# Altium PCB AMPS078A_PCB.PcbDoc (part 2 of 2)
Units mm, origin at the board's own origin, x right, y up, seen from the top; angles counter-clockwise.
Board outline 85 x 120 mm, 4 copper layers (Top Layer, Signal Layer 1, Signal Layer 2, Bottom Layer), stack 1.567 mm thick; 105 components, 52 nets, 354 pads, 440 vias.
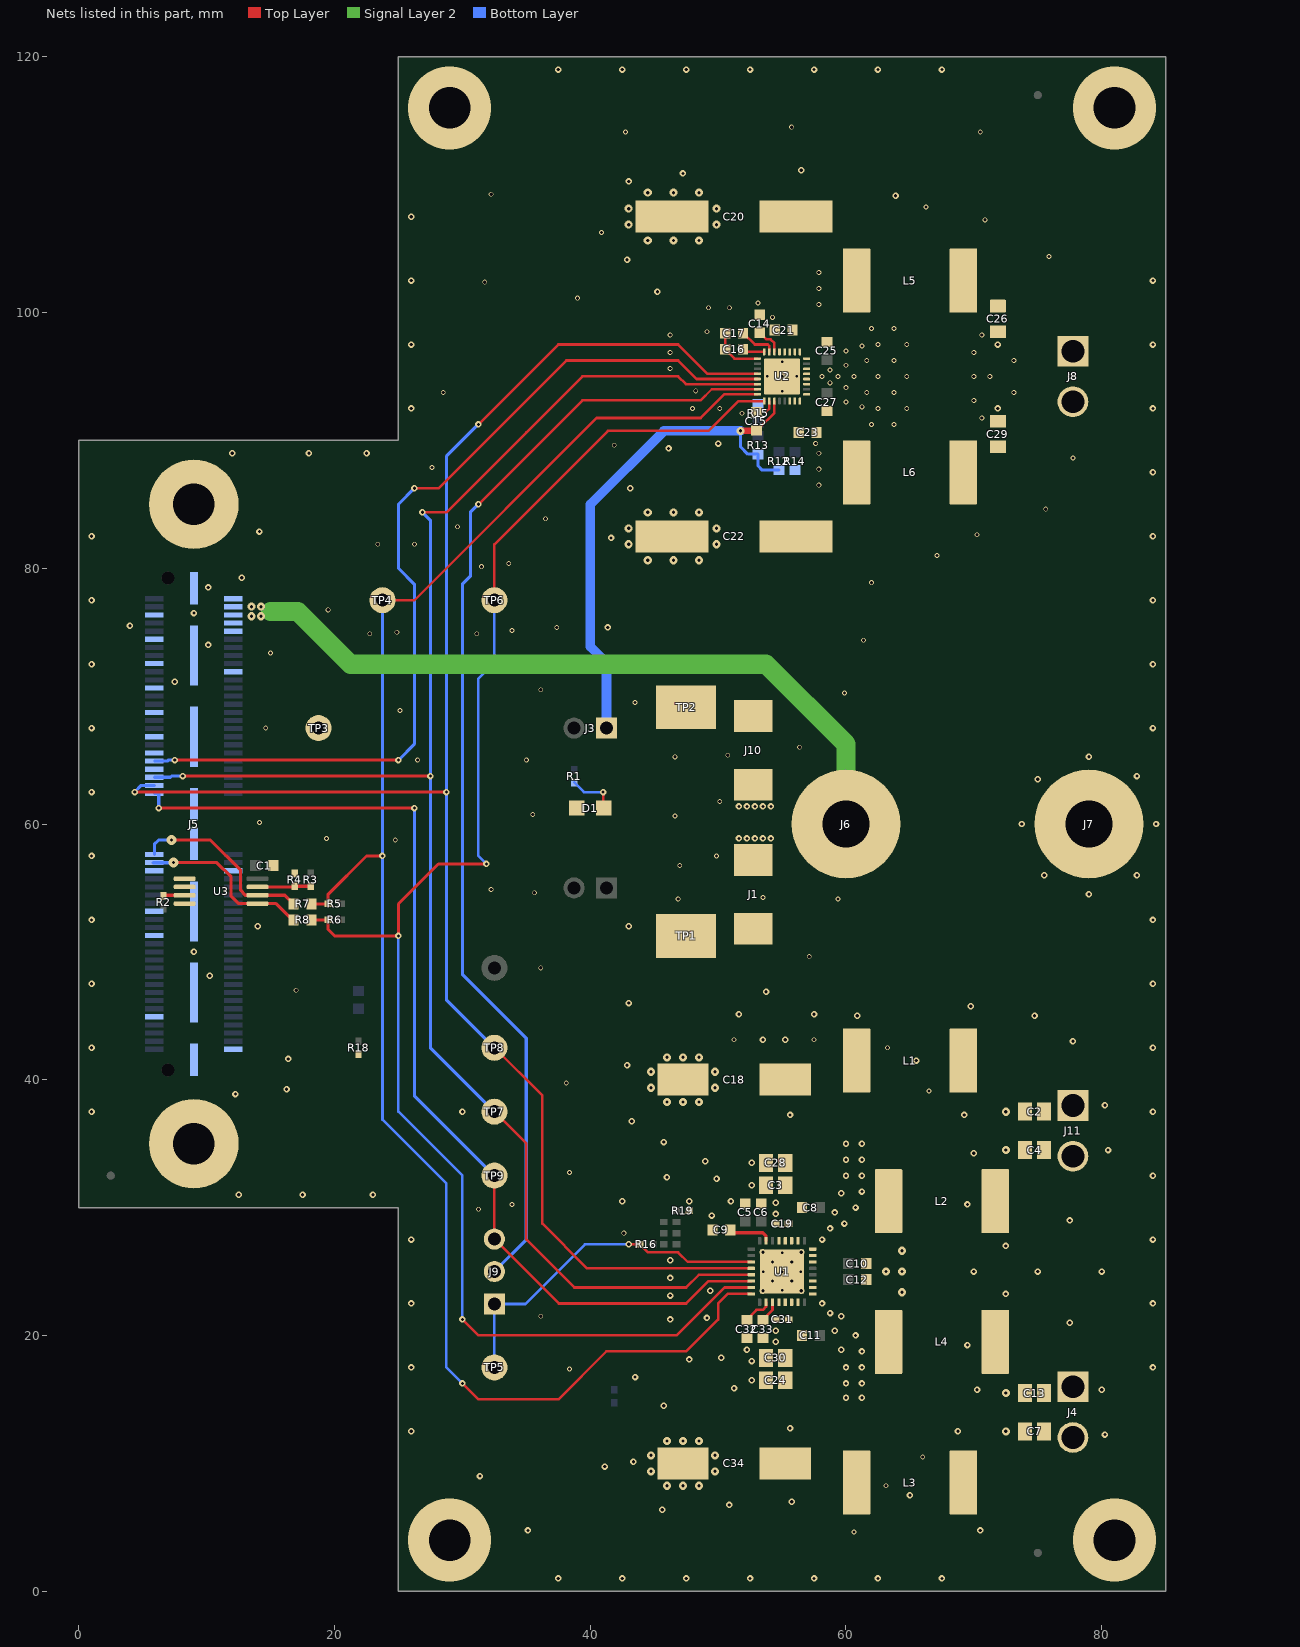
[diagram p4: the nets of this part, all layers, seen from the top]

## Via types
v1: diameter 0.508, hole 0.254, Top Layer to Bottom Layer, tented both sides, 228 vias
v2: diameter 0.381, hole 0.254, Top Layer to Bottom Layer, tented both sides, 125 vias
v3: diameter 0.635, hole 0.254, Top Layer to Bottom Layer, tented both sides, 61 vias
v4: diameter 0.5, hole 0.2, Top Layer to Bottom Layer, 10 vias
v5: diameter 0.508, hole 0.254, Top Layer to Bottom Layer, 8 vias
v6: diameter 6.5, hole 3.25, Top Layer to Bottom Layer, tented both sides, 4 vias
v7: diameter 0.762, hole 0.254, Top Layer to Bottom Layer, tented both sides, 4 vias

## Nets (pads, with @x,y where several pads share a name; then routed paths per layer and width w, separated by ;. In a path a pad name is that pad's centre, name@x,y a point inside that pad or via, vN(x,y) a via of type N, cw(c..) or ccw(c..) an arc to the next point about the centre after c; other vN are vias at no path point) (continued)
DVDD2: C15.1 J3.1 R12.2 R13.2 U2.11 | length 41.9
  Top Layer w0.2: C15.1@53,90.8 53.2,91 53.25,91 54.4,92.15 U2.11@54.4,93.075
  Top Layer w0.25: C15.1@52.95,90.75 C15.1@53,90.8
  Top Layer w0.5: v3(51.75,90.75) C15.1@52.95,90.75
  Bottom Layer w0.25: v3(51.75,90.75) 51.75,89.5 52.325,88.925 R13.2@53.125,88.925 53.125,88 53.45,87.675 R12.2@54.75,87.675
  Bottom Layer w0.75: J3.1@41.27,67.5 41.27,72.605 40,73.875 40,85 45.75,90.75 v3(51.75,90.75)
GND: C1.2 C2.2 C3.1 C4.2 C5.1 C6.2 C7.2 C9.2 C13.2 C14.2 C15.2 C18.2 C19.2 C20.2 C21.2 C22.2 C23.2 C24.1 C26.2 C28.1 C29.2 C30.1 C31.2 C32.2 C33.2 C34.2 D1.2 J5.5 J5.10 J5.11 J5.17 J5.20 J5.23 J5.29 J5.35 J5.39 J5.43 J5.55 J5.56 J5.65 J5.71 J5.91 J5.100 J5.101 J5.102 J5.103 J5.104 J5.105 J5.106 J5.107 J5.108 J7.1 pad.0 R4.1 R14.1 R15.1 R18.1 R19.2 TP3.1 U1.5 U1.20 U1.25 U1.26 U1.31 U1.32 U1.33 U2.10 U2.19 U2.20 U2.21 U2.22 U2.29 U2.33@55,95 U3.1 U3.2 U3.4 | length 0.9
  Top Layer w0.2: 53.75,92.25 54,92.5 U2.10@54,93.075
  other v1: 37.5,1 42.5,1 47.5,1 52.5,1 57.5,1 62.5,1 67.5,1 35.125,4.75 70.5,4.75 45.625,6.375 50.875,6.75 55.75,7 65,7.5 31.375,9 41.125,9.75 43.375,10.125 80.25,12.25 26,12.5 68.75,12.5 55.625,12.75 45.75,14.5 60,15.125 61.25,15.125 70.25,15.75 80,15.75 51.25,15.875 60,16.25 61.25,16.25 52.625,16.5 43.5,16.75 26,17.5 60,17.5 61.25,17.5 84,17.5 52.625,18 47.75,18.125 50.25,18.25 61.25,18.75 52.25,18.875 59.625,18.875 69.5,19.25 54.5,19.5 60.75,20 54.5,20.375 59.125,20.375 77.5,21 46.25,21.25 49.125,21.375 59.625,21.5 58.75,21.75 26,22.5 58.125,22.5 84,22.5 46.25,23.125 72.5,23.25 49.375,23.5 46.25,24.5 70,25 75,25 80,25 46.25,25.875 72.5,27 26,27.5 58.125,27.5 84,27.5 58.75,28.375 59.875,28.75 77.5,29 49.5,29.375 54.5,29.5 59.125,29.625 60.75,30 69.5,30.25 54.5,30.375 42.5,30.5 47.75,30.5 51,30.5 12.5,31 17.5,31 23,31 59.625,31.125 61.25,31.25 52.625,31.75 49.875,32.25 46,32.375 60,32.5 61.25,32.5 84,32.5 52.625,33.5 49,33.625 60,33.75 61.25,33.75 70,34.25 80.5,34.5 60,35 61.25,35 45.75,35.125 43.25,36.75 55.625,37.25 69.25,37.25 1,37.5 30,37.5 84,37.5 80.25,38 12.25,38.875 16.25,39.25 42.875,41.125 65.5,41.5 16.375,41.625 1,42.5 84,42.5 77.75,43 53.5,43.125 55.25,43.125 60.875,45 74.75,45 51.625,45.125 57.5,45.125 69.75,45.75 43,46 53.75,46.875 1,47.5 84,47.5 10.25,48.125 9,50 14,52 43,52 1,52.5 84,52.5 79,54.5 75.5,56 82.75,56 1,57.5 73.75,60 84.25,60 1,62.5 75,63.5 82.75,63.75 79,65.25 1,67.5 84,67.5 7.5,71.125 1,72.5 84,72.5 10.125,74 41.375,75.375 4,75.5 9,76.5 1,77.5 84,77.5 10.125,78.5 12.75,79.25 41.625,82.375 1,82.5 84,82.5 14.125,82.875 43.125,86.25 84,87.5 12,89 18,89 22.5,89 46.125,89.375 50,89.75 26,92.5 71.875,92.5 84,92.5 26,97.5 71.875,97.5 84,97.5 45.25,101.625 26,102.5 84,102.5 42.875,104.125 26,107.5 63.875,109.125 43,110.25 47.25,110.875 56.5,111.125 37.5,119 42.5,119 47.5,119 52.5,119 57.5,119 62.5,119 67.5,119
  other v2: 60.625,4.625 63.125,8.25 66,10.5 38.375,17.375 36.125,21.5 42.625,28 31.25,29.875 33.875,30.25 38.375,32.75 66.5,39.125 38.125,39.75 63.25,42.5 51.25,43.125 57.5,43.125 17,47 36.125,48.75 57.125,49.625 46.875,54.125 59.375,54.125 53.5,54.25 35.625,54.625 32.25,54.875 47,56.75 49.875,57.5 24.75,58.75 19.375,58.875 14.125,60.125 46.625,60.625 35.5,60.75 50.125,61.75 26.5,65 35,65 46.625,65.25 50.75,65.375 56.375,66 14.625,67.5 25.125,68.875 43.5,69.5 59.875,70.25 36.125,70.5 15,73.375 61.375,74.375 22.75,74.875 31.125,74.875 24.875,75 33.875,75.125 37.375,75.375 19.5,76.75 62,78.875 31.5,80.125 33.625,80.375 67.125,81 23.375,81.875 26.25,81.875 70.25,82.625 29.625,83.25 36.5,83.875 75.625,84.625 57.875,86.5 57.875,87.75 27.625,87.875 77.75,88.625 57.875,89 41.875,89.625 57.625,89.75 62,91.25 63.75,91.25 70.625,91.75 51.875,92.125 48,92.5 50.125,92.5 62.5,92.5 64.75,92.5 61.25,92.625 60,93 70,93.125 28.5,93.75 61.625,93.75 63.75,93.75 73.125,93.75 48.25,93.875 60,94.125 58.75,94.5 58.125,95 59.375,95 60.625,95 62.5,95 64.75,95 70,95 71.25,95 77.5,95 58.75,95.5 46.25,95.625 60,95.875 61.625,96.25 63.75,96.25 73.125,96.25 46.25,96.875 70,96.875 60,97 61.25,97.375 62.5,97.5 64.75,97.5 46.25,98.25 70.625,98.25 49.125,98.5 62,98.75 63.75,98.75 54.25,99.625 49.25,100.375 50.875,100.375 57.875,100.625 53.125,100.75 39,101.125 57.875,101.875 31.75,102.375 57.875,103.125 75.875,104.375 40.875,106.25 70.875,107.25 66.25,108.25 32.25,109.25 42.75,114.125 70.5,114.125 55.75,114.5
  other v3: 72.5,12.5 72.5,15.5 64.375,23.375 63.125,25 64.375,25 64.375,26.625 72.5,34.5 72.5,37.5
  other v4: 55,23.525 53.525,25 55,25 56.475,25 55,26.475 55,93.85 53.85,95 55,95 56.15,95 55,96.15
  other v5: 53.5,23.5 56.5,23.5 54.25,24.25 55.75,24.25 54.25,25.75 55.75,25.75 53.5,26.5 56.5,26.5
  other v6: 29,4 81,4 29,116 81,116
Left+: C2.1 J11.1 L1.2
Left-: C4.1 J11.2 L2.2
LRCLK: J5.47 TP8.1 U1.12 U2.4 | length 135.9
  Top Layer w0.2: v1(31.25,91.25) 37.5,97.5 46.875,97.5 49.175,95.2 U2.4@53.075,95.2 ; TP8.1@32.5,42.5 36.25,38.75 36.25,28.75 39.75,25.25 U1.12@52.6,25.25
  Top Layer w0.25: v1(4.375,62.5) v1(28.75,62.5)
  Bottom Layer w0.25: v1(4.375,62.5) 4.891,63.016 J5.47@5.914,63.016 ; v1(31.25,91.25) 28.75,88.75 v1(28.75,62.5) 28.75,46.25 TP8.1@32.5,42.5
MCLK: J5.41 U2.5 | length 73.5
  Top Layer w0.2: v1(26.25,86.25) 28.125,86.25 38.125,96.25 46.875,96.25 48.325,94.8 U2.5@53.075,94.8
  Top Layer w0.25: v1(7.5,65) v1(25,65)
  Bottom Layer w0.25: J5.41@5.914,64.921 6.921,64.921 7,65 v1(7.5,65) ; v1(25,65) 26.25,66.25 26.25,78.75 25,80 25,85 v1(26.25,86.25)
NetC9_1: C9.1 U1.7 | length 3.4
  Top Layer w0.254: C9.1@50.95,28.25 51.173,28.027 53.481,28.027 53.75,27.758 U1.7@53.75,27.4
NetC14_1: C14.1 U2.30 | length 2.2
  Top Layer w0.2: C14.1@53.25,98.425 53.775,97.9 54.1,97.9 54.4,97.6 U2.30@54.4,96.925
NetC16_1: C16.1 C17.1 U2.1 | length 4.1
  Top Layer w0.2: C17.1@50.55,98.375 C16.1@50.55,97.125 51.275,96.4 U2.1@53.075,96.4
NetC16_2: C16.2 U2.32 | length 1.7
  Top Layer w0.2: C16.2@51.95,97.125 52.15,96.925 U2.32@53.6,96.925
NetC17_2: C17.2 U2.31 | length 2.9
  Top Layer w0.2: C17.2@51.95,98.375 52,98.375 52.875,97.5 53.875,97.5 54,97.375 U2.31@54,96.925
NetC32_1: C32.1 U1.18 | length 2.3
  Top Layer w0.2: C32.1@52.25,21.2 52.25,21.25 53,22 53.5,22 53.75,22.25 U1.18@53.75,22.6
NetC33_1: C33.1 U1.19 | length 1.7
  Top Layer w0.2: C33.1@53.5,21.2 53.5,21.25 54.25,22 U1.19@54.25,22.6
NetD1_1: D1.1 R1.1 | length 3.8
  Top Layer w0.2: v1(41,62.5) 41,61.3 D1.1@41.05,61.25
  Bottom Layer w0.2: R1.1@38.75,63.25 39.5,62.5 v1(41,62.5)
NetR2_1: R2.1 U3.3 | length 1.7
  Top Layer w0.25: R2.1@6.625,54.375 6.675,54.425 U3.3@8.275,54.425
NetR3_2: R3.2 R4.2 U3.7 | length 4.2
  Top Layer w0.254: U3.7@13.975,55.075 16.7,55.075 R4.2@16.875,55.25 ; R4.2@16.875,55.125 R3.2@18.125,55.125
OUT_A+: C8.2 L1.1 U1.2
OUT_A-: C10.2 L2.1 U1.30
OUT_B+: C11.2 L3.1 U1.23
OUT_B-: C12.2 L4.1 U1.27
OUT_N: C27.2 L6.1 U2.16 U2.17
OUT_P: C25.2 L5.1 U2.24 U2.25
PVDD: J1.1 J5.2 J5.4 J5.6 J5.8 J6.1 J10.1 | length 55.5
  Signal Layer 2 w1.5: 15,76.625 17.125,76.625 21.25,72.5 53.75,72.5 60,66.25 J6.1@60,60
  other v1: 51.625,58.875 52.25,58.875 52.875,58.875 53.5,58.875 54.125,58.875 51.625,61.375 52.25,61.375 52.875,61.375 53.5,61.375 54.125,61.375
  other v3: 13.5,76.25 14.25,76.25 13.5,77 14.25,77
PVDD1: C3.2 C18.1 C19.1 C24.2 C28.2 C30.2 C31.1 C34.1 J1.2 TP1.1 U1.3 U1.4 U1.21 U1.22
  other v3: 46,8.25 47.25,8.25 48.5,8.25 44.75,9.375 49.75,9.375 44.75,10.625 49.75,10.625 46,11.75 47.25,11.75 48.5,11.75 46,38.25 47.25,38.25 48.5,38.25 44.75,39.375 49.75,39.375 44.75,40.625 49.75,40.625 46,41.75 47.25,41.75 48.5,41.75
PVDD2: C20.1 C21.1 C22.1 C23.1 J10.2 TP2.1 U2.14 U2.15 U2.26 U2.27 U2.28
  other v3: 44.5,80.625 46.5,80.625 48.5,80.625 43,81.875 49.875,81.875 43,83.125 49.875,83.125 44.5,84.375 46.5,84.375 48.5,84.375 44.5,105.625 46.5,105.625 48.5,105.625 43,106.875 49.875,106.875 43,108.125 49.875,108.125 44.5,109.375 46.5,109.375 48.5,109.375
Right+: C7.1 J4.2 L3.2
Right-: C13.1 J4.1 L4.2
SCL: R5.1 R7.1 TP4.1 U1.16 U2.8 | length 134.6
  Top Layer w0.2: TP4.1@23.75,77.5 26.25,77.5 40.5,91.75 48.625,91.75 50.475,93.6 U2.8@53.075,93.6 ; v1(30,16.25) 31.25,15 37.5,15 41.25,18.75 47.5,18.75 50,21.25 50,22.5 50.75,23.25 U1.16@52.6,23.25
  Top Layer w0.25: R7.1@18.2,53.75 R5.1@19.5,53.75 19.5,54.5 22.5,57.5 v1(23.75,57.5)
  Bottom Layer w0.2: TP4.1@23.75,77.5 v1(23.75,57.5) 23.75,36.875 28.75,31.875 28.75,17.5 v1(30,16.25)
SCL-PPCMB_OUT: J5.51 R7.2 U3.6 | length 15.8
  Top Layer w0.25: v7(7.25,58.75) 10.279,58.75 12.649,56.38 12.649,54.805 ; 13.024,54.43 16.12,54.43 R7.2@16.8,53.75
  Top Layer w0.254: 12.649,54.805 13.024,54.43 13.029,54.425 U3.6@13.975,54.425
  Bottom Layer w0.254: J5.51@5.914,57.619 5.914,58.414 6.25,58.75 v7(7.25,58.75)
SCLK: J5.45 TP7.1 U1.13 U2.6 | length 132.3
  Top Layer w0.2: v1(26.875,84.375) 28.75,84.375 35,90.625 39.375,95 46.875,95 47.475,94.4 U2.6@53.075,94.4 ; TP7.1@32.5,37.5 35,35 35,27.5 38.75,23.75 47.5,23.75 48.5,24.75 U1.13@52.6,24.75
  Top Layer w0.25: v1(8.125,63.75) v1(27.5,63.75)
  Bottom Layer w0.25: J5.45@5.914,63.651 7.151,63.651 7.25,63.75 v1(8.125,63.75) ; v1(26.875,84.375) 27.5,83.75 v1(27.5,63.75) 27.5,42.5 TP7.1@32.5,37.5
SDA: R6.1 R8.1 TP6.1 U1.15 U2.9 | length 126.7
  Top Layer w0.2: v1(30,21.25) 31.25,20 46.75,20 50.5,23.75 U1.15@52.6,23.75 ; TP6.1@32.5,77.5 32.5,81.875 41.375,90.75 49.25,90.75 51.575,93.075 U2.9@53.6,93.075
  Top Layer w0.25: R8.1@18.2,52.5 R6.1@19.5,52.5 19.5,51.75 20,51.25 v1(25,51.25) 25,53.75 28.125,56.875 v1(31.875,56.875)
  Bottom Layer w0.2: v1(25,51.25) 25,37.5 30,32.5 v1(30,21.25) ; v1(31.875,56.875) 31.25,57.5 31.25,71.375 32.5,72.625 TP6.1@32.5,77.5
SDA-PPCMB_OUT: J5.53 R8.2 U3.5 | length 13.9
  Top Layer w0.25: v7(7.414,56.984) 10.789,56.984 11.914,55.859 11.914,54.359
  Top Layer w0.254: 11.914,54.359 12.498,53.775 U3.5@13.975,53.775 15.425,53.775 R8.2@16.95,52.25
  Bottom Layer w0.25: J5.53@5.828,56.967 v7@7.398,56.967
SDIN: J5.49 J9.3 TP9.1 U1.14 | length 80.7
  Top Layer w0.2: TP9.1@32.5,32.5 J9.3@32.5,27.54 37.54,22.5 47.5,22.5 49.25,24.25 U1.14@52.6,24.25
  Top Layer w0.25: v1(6.25,61.25) v1(26.25,61.25)
  Bottom Layer w0.25: J5.49@5.914,62.381 6.244,62.381 6.25,62.375 v1(6.25,61.25) ; v1(26.25,61.25) 26.25,38.75 TP9.1@32.5,32.5
SDIN-5720: J9.2 U2.7 | length 89.2
  Top Layer w0.2: v1(31.25,85) 39.375,93.125 48.625,93.125 49.5,94 U2.7@53.075,94
  Bottom Layer w0.25: v1(31.25,85) 30.625,84.375 30.625,79.375 30,78.75 30,48.25 35,43.25 35,27.5 J9.2@32.5,25
SDOUT: J9.1 R16.1 TP5.1 U1.11 | length 27.6
  Top Layer w0.2: v1(43,27.125) R16.1@43.875,27.125 44.5,26.5 46.875,26.5 47.625,25.75 U1.11@52.6,25.75
  Bottom Layer w0.2: TP5.1@32.5,17.5 J9.1@32.5,22.46 34.92,22.46 39.585,27.125 v1(43,27.125)
SUB+: C26.1 J8.1 L5.2
SUB-: C29.1 J8.2 L6.2
pads on no net: FID1.1 FID2.1 FID3.1 FID4.1 FID5.1 FID6.1 J5.1 J5.3 J5.7 J5.9 J5.12 J5.13 J5.14 J5.15 J5.16 J5.18 J5.19 J5.21 J5.24 J5.25 J5.26 J5.27 J5.28 J5.30 J5.31 J5.32 J5.33 J5.34 J5.36 J5.37 J5.38 J5.40 J5.42 J5.44 J5.46 J5.48 J5.50 J5.52 J5.54 J5.57 J5.59 J5.61 J5.63 J5.66 J5.67 J5.68 J5.69 J5.70 J5.72 J5.73 J5.74 J5.75 J5.76 J5.77 J5.79 J5.80 J5.81 J5.82 J5.83 J5.84 J5.85 J5.86 J5.87 J5.88 J5.89 J5.92 J5.93 J5.94 J5.95 J5.96 J5.97 J5.98 J5.99 J5.MH1 J5.MH2 SH-J1.0 SH-J2.0 SH-J3.0 U1. U2.33@54.285,94.285 U2.33@54.285,95.715 U2.33@55.715,94.285 U2.33@55.715,95.715

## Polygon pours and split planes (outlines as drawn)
Left- on Top Layer "OUT3- Top Copper" (solid, pour order 280): 70.5,28 70.5,33 74.75,33 75.25,33.5 75.25,35.25 79,35.25 79,32.75 74.25,28
OUT_A- on Top Layer "OUT_A- Top Copper" (solid, pour order 278): 57.15,25.625 58.875,25.625 59.5,26.25 61,26.25 61.125,26.125 61.125,25.125 62,25.125 64.5,27.625 64.5,33 62.25,33 62.25,30.375 57.75,25.875 57.15,25.875
OUT_A+ on Top Layer "OUT_A+ Top Copper" (solid, pour order 277): 56.125,27.125 56.125,37.125 57.5,38.5 57.5,41.75 59.75,44 62,44 62,38.25 59,35.25 59,32.25 57.25,30.5 57.25,28.75 56.375,27.875 56.375,27.125 56.35,27.1 56.15,27.1
Left+ on Top Layer "OUT3+ Top Copper" (solid, pour order 279): 68,44 68,39 74.75,39 75.25,38.5 75.25,36.75 79,36.75 79,39.25 74.25,44
Right+ on Top Layer "OUT4+ Top Copper" (solid, pour order 283): 68,6 68,11 74.75,11 75.25,11.5 75.25,13.25 79,13.25 79,10.75 74.25,6
PVDD1 on Top Layer "PVDD1 Top Copper" (solid, pour order 293): 55.1,27.15 55.15,27.1 55.85,27.1 55.9,27.15 55.9,36.2 53.85,38.25 51.25,38.25 50.25,39.25 50.25,45.25 54.25,49.25 54.25,53.125 45.125,53.125 44.25,52.25 44.25,38.5 47.75,35 53.375,35 54.125,34.25 54.125,31.625 55.1,30.65
OUT_B+ on Top Layer "OUT_B+ Top Copper" (solid, pour order 281): 56.125,22.875 56.125,12.875 57.5,11.5 57.5,8.25 59.75,6 62,6 62,11.75 59,14.75 59,17.75 57.25,19.5 57.25,21.25 56.375,22.125 56.375,22.875 56.35,22.9 56.15,22.9
OUT_B- on Top Layer "OUT_B- Top Copper" (solid, pour order 282): 57.15,24.375 58.875,24.375 59.5,23.75 61,23.75 61.125,23.875 61.125,24.875 62,24.875 64.5,22.375 64.5,17 62.25,17 62.25,19.625 57.75,24.125 57.15,24.125
Right- on Top Layer "OUT4- Top Copper" (solid, pour order 284): 70.5,22 70.5,17 74.75,17 75.25,16.5 75.25,14.75 79,14.75 79,17.25 74.25,22
PVDD1 on Top Layer "PVDD1 Top Copper" (solid, pour order 292): 55.1,22.85 55.15,22.9 55.85,22.9 55.9,22.85 55.9,13.775 53.875,11.75 51.25,11.75 50.25,10.75 50.25,8.5 49.5,7.75 45,7.75 44.25,8.5 44.25,11.5 47.75,15 53.375,15 54.125,15.75 54.125,18.375 55.1,19.35
3.3V on Top Layer "3.3V Top Copper" (solid, remove dead copper, pour order 285): 9.375,55.5 9.875,56 11,56 11.5,55.5 11.5,54 11,53.5 9.875,53.5 9.375,54 9.375,55.5
GND on Top Layer "GND Top Copper" (solid, remove dead copper, pour order 298): 25.5,117.5 27.5,119.5 82.5,119.5 84.5,117.5 84.5,2.5 82.5,0.5 27.5,0.5 25.5,2.5 25.5,30.5 7.5,30.5 0.5,37.5 0.5,82.5 7.5,89.5 25.5,89.5
OUT_P on Top Layer "OUT_P Top Copper" (solid, remove dead copper, pour order 273): 56.65,96.3 56.65,96.5 56.5,96.65 56.3,96.65 56.3,97.8 58.75,100.25 58.75,104 59.75,105 61.9,105 61.9,100 58.9,97 57.95,97 57.25,96.3
OUT_N on Top Layer "OUT_N Top Copper" (solid, remove dead copper, pour order 274): 57.25,93.7 56.65,93.7 56.65,93.5 56.5,93.35 56.3,93.35 56.3,92.2 57,91.5 58,91.5 58.75,90.75 58.75,86 59.75,85 61.9,85 61.9,90 58.9,93 57.95,93
PVDD2 on Top Layer "PVDD2 Top Copper" (solid, remove dead copper, pour order 295): 55.1,96.65 55.1,99.9 53.75,101.25 47.5,101.25 42.5,106.25 42.5,108.75 43.75,110 48.75,110 50.375,108.375 50.375,106.25 51,105.625 55.625,105.625 57,104.25 57,98.875 56.1,97.975 56.1,96.65
PVDD2 on Top Layer "PVDD2 Top Copper" (solid, remove dead copper, pour order 296): 50.375,83.75 51,84.375 55.625,84.375 57,85.75 57,91.175 56.1,92.075 56.1,93.35 55.5,93.35 55.5,90.5 53.75,88.75 47.5,88.75 42.5,83.75 42.5,72.5 45,70 45,67.375 45.25,67.125 54.25,67.125 54.25,70.75 50.375,74.625
SUB+ on Top Layer "SUB+ Top Copper" (solid, remove dead copper, pour order 275): 68,105 72.25,105 79,98.25 79,95.75 76.5,95.75 72.25,100 68,100
SUB- on Top Layer "SUB- Top Copper" (solid, remove dead copper, pour order 276): 68,85 72.25,85 79,91.75 79,93.75 78.5,94.25 76.5,94.25 72.25,90 68,90
PVDD on Top Layer "PVDD Top Copper" (solid, remove dead copper, pour order 288): 51.25,64.375 62,64.375 64.5,61.875 64.5,58.125 62,55.625 51.375,55.625 51.125,55.875 51.125,64.25
PVDD on Bottom Layer "PVDD Bottom Copper" (solid, remove dead copper, pour order 290): 11.25,77.875 14.125,77.875 14.625,77.375 14.625,75.875 14.25,75.5 11.25,75.5
3.3V on Bottom Layer "3.3V Bottom Copper" (solid, remove dead copper, pour order 287): 10.225,55.925 9.675,55.375 9.675,54.175 10.25,53.6 12.825,53.6 12.825,55.925
GND on Bottom Layer "GND Bottom Copper" (solid, remove dead copper, pour order 301): 25.5,117.5 27.5,119.5 82.5,119.5 84.5,117.5 84.5,2.5 82.5,0.5 27.5,0.5 25.5,2.5 25.5,30.5 7.5,30.5 0.5,37.5 0.5,82.5 7.5,89.5 25.5,89.5
PVDD1 on Bottom Layer "PVDD1 Bottom Copper" (solid, remove dead copper, pour order 294): 45,42.25 61.5,42.25 68.75,35 68.75,15 61.5,7.75 45,7.75 44.25,8.5 44.25,11.5 45,12.25 59.75,12.25 65,17.5 65,32.5 59.75,37.75 45,37.75 44.25,38.5 44.25,41.5
PVDD2 on Bottom Layer "PVDD2 Bottom Copper" (solid, remove dead copper, pour order 297): 43.75,110 61.25,110 69.125,102.125 69.125,87.875 61.25,80 43.75,80 42.5,81.25 42.5,83.75 43.75,85 60,85 65.375,90.375 65.375,99.625 60,105 43.75,105 42.5,106.25 42.5,108.75
PVDD on Bottom Layer "PVDD Bottom Copper" (solid, remove dead copper, pour order 291): 51.25,64.375 62,64.375 64.5,61.875 64.5,58.125 62,55.625 51.375,55.625 51.125,55.875 51.125,64.25
3.3V on Signal Layer 2 "3.3V Copper Layer 3" (solid, remove dead copper, pour order 286): 9.375,55.5 9.875,56 11,56 11.5,55.5 11.5,54 11,53.5 9.75,53.5 9.375,53.875
GND on Signal Layer 2 "GND  Copper Layer 3" (solid, remove dead copper, pour order 300): 25.5,117.5 27.5,119.5 82.5,119.5 84.5,117.5 84.5,2.5 82.5,0.5 27.5,0.5 25.5,2.5 25.5,30.5 7.5,30.5 0.5,37.5 0.5,82.5 7.5,89.5 25.5,89.5
PVDD on Signal Layer 2 "PVDD Copper Layer 3" (solid, remove dead copper, pour order 289): 11.25,77.875 14.125,77.875 14.625,77.375 15.375,77.375 15.375,75.875 14.625,75.875 14.25,75.5 11.25,75.5
GND on Signal Layer 1 "GND Copper Layer 2" (solid, remove dead copper, pour order 299): 25.5,117.5 27.5,119.5 82.5,119.5 84.5,117.5 84.5,2.5 82.5,0.5 27.5,0.5 25.5,2.5 25.5,30.5 7.5,30.5 0.5,37.5 0.5,82.5 7.5,89.5 25.5,89.5

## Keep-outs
Keep-Out Layer:
  lines w0.254: -0.25,29.75 -0.25,90.25 24.75,90.25 24.75,120.25 85.25,120.25 85.25,-0.25 24.75,-0.25 24.75,29.75 -0.25,29.75

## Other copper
Top Layer:
  text ".Layer_Name" at 14.656,-21.806 h1.52
Signal Layer 1:
  text ".Layer_Name" at 14.656,-21.806 h1.52
Signal Layer 2:
  text ".Layer_Name" at 14.656,-21.806 h1.52
Bottom Layer:
  text ".Layer_Name" at 14.656,-21.806 h1.52

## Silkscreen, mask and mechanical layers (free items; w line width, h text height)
Top Overlay:
  lines w0.2: 59.85,84.75 59.85,82.35 70.15,82.35 70.15,84.75 ; 59.85,90.25 59.85,92.65 70.15,92.65 70.15,90.25 ; 59.85,99.75 59.85,97.35 70.15,97.35 70.15,99.75 ; 59.85,105.25 59.85,107.65 70.15,107.65 70.15,105.25
  lines w0.25: 59.85,5.625 59.85,3.35 70.15,3.35 70.15,5.625 ; 59.85,11.375 59.85,13.65 70.15,13.65 70.15,11.375 ; 59.85,38.625 59.85,36.35 70.15,36.35 70.15,38.625 ; 59.85,44.375 59.85,46.65 70.15,46.65 70.15,44.375 ; 62.35,16.625 62.35,14.35 72.65,14.35 72.65,16.625 ; 62.35,22.375 62.35,24.65 72.65,24.65 72.65,22.375 ; 62.35,27.625 62.35,25.35 72.65,25.35 72.65,27.625 ; 62.35,33.375 62.35,35.65 72.65,35.65 72.65,33.375
  text "+" at 77.125,98.75 h1.5
  text "-" at 77.25,90.75 h1.25
  text "PVDD RANGE" at 63.125,50.375 h1.5
  text "4.5V - 26.4V" at 63.625,48.375 h1.25
  text "+" at 77,39.625 h1.5
  text "-" at 77.25,31.625 h1.25
  text "SDIN" at 34.25,26.75 h1.5
  text "SDIN-5825" at 34.25,24.25 h1.25
  text "SDOUT" at 34.25,21.625 h1.5
  text "-" at 77.125,17.25 h1.5
  text "2.1 Scalable" at 26.5,12 h2
  text "+" at 77.25,9.25 h1.25
  text "Sound Bar" at 27,9 h2
  text "TAS5825MEVM-SB" at 34.5,0.5 h1.75
  text "AMPS078A" at 59.125,0.5 h1.5
  text ".Layer_Name" at 14.656,-21.806 h1.52
Bottom Overlay:
  text ".Layer_Name" at 14.656,-21.806 h1.52
Top Paste:
  text ".Layer_Name" at 14.656,-21.806 h1.52
Bottom Paste:
  text ".Layer_Name" at 14.656,-21.806 h1.52
Top Solder:
  text ".Layer_Name" at 14.656,-21.806 h1.52
Bottom Solder:
  text ".Layer_Name" at 14.656,-21.806 h1.52
Drill Guide:
  text ".Layer_Name" at 95.25,29.25 h1.52
M1 Board Outline:
  the board outline again, w0.254
  text ".Layer_Name" at 56.75,-21.875 h1.52
M2 Board Dimensions:
  text ".Layer_Name" at 82.5,-22 h1.52
M3 3D STEP Top:
  text ".Layer_Name" at 14.656,-21.806 h1.52
M4 3D STEP Bottom:
  text ".Layer_Name" at 14.656,-21.806 h1.52
M5 Assembly Top:
  lines w0.254: -7.417,-23.626 160.223,-23.626 ; -7.417,-18.462 160.274,-18.462 ; -7.417,-13.297 -7.417,-28.791 94.31,-28.791 160.274,-28.791 160.274,-13.297 -7.404,-13.297 -7.404,-28.791 32.614,-28.791 ; 55.194,-28.791 55.194,-13.297 ; 87.376,-18.462 87.376,-13.297 ; 108.712,-18.462 108.712,-13.297 ; 124.511,-28.956 124.511,-23.804
  text "COMPONENTS MARKED 'DNP' SHOULD NOT BE POPULATED." at 29.299,-8.09 h1.52
  text "ASSEMBLY VARIANT:" at 29.286,-11.024 h1.52
  text ".VariantName" at 55.601,-11.024 h1.52
  text "PCB VIEWED FROM TOP SIDE" at -5.804,-16.654 h1.52
  text "BOARD #:" at 57.099,-16.654 h1.52
  text ".PRJ_Number" at 70.955,-16.654 h1.52
  text "REV:" at 92.405,-16.654 h1.52
  text ".PCB_Rev" at 99.809,-16.654 h1.52
  text "SVN REV:" at 113.69,-16.654 h1.52
  text ".VersionControl_RevNumber" at 126.543,-16.654 h1.52
  text "PLOT NAME =" at -5.804,-27.034 h1.52
  text ".plot_File_Name" at 14.656,-27.034 h1.52
  text "GENERATED    :" at 57.15,-27.034 h1.52
  text ".Print_Date" at 79.235,-27.034 h1.52
  text ".Print_Time" at 97.752,-27.034 h1.52
  text "TEXAS INSTRUMENTS" at 129.87,-27.034 h1.52
M6 Assembly Bottom:
  lines w0.254: -7.429,-18.474 160.261,-18.474 ; -7.379,-23.639 160.261,-23.639 ; 28.334,-28.969 28.334,-23.817 ; 44.133,-18.474 44.133,-13.31 ; 65.468,-18.474 65.468,-13.31 ; 97.65,-28.804 97.65,-13.31 ; 120.231,-28.804 160.249,-28.804 160.249,-13.31 -7.429,-13.31 -7.429,-28.804 58.534,-28.804 160.261,-28.804 160.261,-13.31
  text "COMPONENTS MARKED 'DNP' SHOULD NOT BE POPULATED." at 154.991,-8.077 h1.52
  text ".VariantName" at 128.473,-11.024 h1.52
  text "ASSEMBLY VARIANT:" at 154.864,-11.024 h1.52
  text ".VersionControl_RevNumber" at 26.302,-16.667 h1.52
  text "SVN REV:" at 39.154,-16.667 h1.52
  text ".PCB_Rev" at 53.035,-16.667 h1.52
  text "REV:" at 60.439,-16.667 h1.52
  text ".PRJ_Number" at 81.89,-16.667 h1.52
  text "BOARD #:" at 95.745,-16.667 h1.52
  text "PCB VIEWED FROM BOTTOM SIDE" at 158.648,-16.667 h1.52
  text "TEXAS INSTRUMENTS" at 22.974,-27.047 h1.52
  text ".Print_Time" at 55.093,-27.047 h1.52
  text ".Print_Date" at 73.609,-27.047 h1.52
  text "GENERATED    :" at 95.694,-27.047 h1.52
  text ".plot_File_Name" at 138.189,-27.047 h1.52
  text "PLOT NAME =" at 158.648,-27.047 h1.52
M9 Title Sheet:
  drawing of 57 lines, arcs and shapes, not listed
  text "1" at 18.792,204.127 h1.78
  text "2" at 82.182,204.127 h1.78
  text "3" at 145.411,204.127 h1.78
  text "4" at 209.08,204.127 h1.78
  text "5" at 272.555,204.127 h1.78
  text "6" at 336.182,204.127 h1.78
  text "A" at -10.579,175.095 h1.78
  text "A" at 365.341,175.095 h1.78
  text "B" at -10.579,114.643 h1.78
  text "B" at 365.341,114.643 h1.78
  text "C" at -10.579,54.318 h1.78
  text "C" at 365.341,54.318 h1.78
  text "PROJECT TITLE:" at 288.125,7.048 h1.14
  text ".PRJ_Title" at 289.395,3.662 h1.78
  text "DESIGNED FOR:" at 288.125,-0.597 h1.14
  text ".PRJ_Customer" at 289.395,-4.153 h1.78
  text "D" at -10.579,-5.88 h1.78
  text "D" at 365.341,-5.88 h1.78
  text "FILE NAME:" at 288.125,-8.217 h1.14
  text ".PCB_File_Name_No_Path" at 289.395,-11.265 h1.78
  text "Texas Instruments (TI) and/or its licensors do not warrant the accuracy or completeness of this specification" at 161.9,-15.376 h1.14
  text "ENGINEER:" at 288.125,-15.583 h1.14
  text "LAYOUT BY:" at 326.352,-15.583 h1.14
  text "or any information contained therein. TI and/or its licensors do not warrant that this design will meet" at 160.757,-18.237 h1.14
  text ".PRJ_Engineer" at 289.395,-19.52 h1.78
  text ".PCB_Layout" at 327.635,-19.52 h1.78
  text "the specifications, will be suitable for your application or fit for any particular purpose, or will operate in" at 160.757,-21.099 h1.14
  text "ALTIUM DESIGNER VERSION:" at 326.352,-23.457 h1.14
  text "an implementation. TI and/or its licensors do not warrant that the design is production worthy. You should" at 160.757,-23.961 h1.14
  text "completely validate and test your design implementation to confirm the system functionality for your application." at 161.9,-26.822 h1.14
  text ".print_Scale" at 289.395,-26.843 h1.78
  text ".Application_BuildNumber" at 327.635,-26.843 h1.78
  text "1" at 18.792,-32.093 h1.78
  text "2" at 82.182,-32.093 h1.78
  text "3" at 145.411,-32.093 h1.78
  text "4" at 209.08,-32.093 h1.78
  text "5" at 272.555,-32.093 h1.78
  text "6" at 336.182,-32.093 h1.78
M10 Fab Notes:
  drawing of 189 lines, arcs and shapes, not listed
  text ".Layer_Name" at 287.25,164.5 h1.52
  text "DESIGN INFORMATION" at 314.503,161.447 h1.52
  text "MIN. TRACK WIDTH:" at 298.131,158.091 h1.52
  text "8" at 325.976,158.091 h1.52
  text "MIL" at 329.907,158.091 h1.52
  text "MIN. CLEARANCE:" at 298.131,154.938 h1.52
  text "0.2" at 324.452,154.938 h1.52
  text "mm" at 329.907,154.938 h1.52
  text "MIN. VIA PAD SIZE:" at 298.131,151.785 h1.52
  text "20" at 325.214,151.785 h1.52
  text "MIL" at 329.907,151.785 h1.52
  text "0.05mm (2MIL)" at 315.784,148.486 h1.52
  text "MINIMUM ANNULAR RING" at 289.769,148.277 h1.52
  text "EXTERNAL" at 333.768,148.277 h1.52
  text "PER" at 294.849,145.48 h1.52
  text "IPC-D-275 CLASS 2 LEVEL C" at 300.437,145.48 h1.52
  text "MIL, HOLES" at 338.238,142.928 h1.52
  text "+/-" at 328.27,142.709 h1.52
  text "+/-" at 349.961,142.709 h1.52
  text "REGISTRATION TOLERANCES:" at 289.769,142.682 h1.52
  text "METAL" at 320.243,142.682 h1.52
  text "5" at 334.879,142.683 h1.52
  text "3" at 356.037,142.683 h1.52
  text "MIL" at 358.99,142.682 h1.52
  text "HOLE SIZE TOLERANCE (UNLESS OTHERWISE SPECIFIED):" at 289.769,140.185 h1.52
  text "+/-" at 349.961,140.112 h1.52
  text "3" at 356.037,140.085 h1.52
  text "MIL" at 358.99,140.085 h1.52
  text "MATERIAL:" at 287.87,136.589 h1.52
  text "FR-4 High Tg" at 312.926,133.324 h1.52
  text "X" at 309.257,133.122 h1.52
  text "FR-408" at 298.563,133.007 h1.52
  text "OTHER" at 336.358,133.007 h1.52
  text "62 MIL (1.6mm) +/-10%" at 306.694,129.374 h1.52
  text "X" at 303.643,129.312 h1.52
  text "THICKNESS:" at 289.769,129.165 h1.52
  text "OTHER" at 339.33,129.165 h1.52
  text "TOLERANCE:" at 289.769,125.652 h1.52
  text "X" at 311.314,125.652 h1.52
  text "ANSI IPC-6012 TYPE 3 CLASS 2" at 315.836,125.652 h1.52
  text "OTHER +/-" at 315.835,121.989 h1.52
  text "BOW & TWIST:" at 289.769,118.302 h1.52
  text "X" at 311.314,118.302 h1.52
  text "ANSI IPC-6012 TYPE 3 CLASS 2" at 315.836,118.302 h1.52
  text "OTHER +/-" at 315.835,114.576 h1.52
  text "DRILLING:" at 287.87,111.258 h1.52
  text "NC_DRILL FILES" at 332.599,108.586 h1.52
  text "REFERENCE:" at 289.769,108.486 h1.52
  text "X" at 306.463,108.484 h1.52
  text "AS SHOWN" at 310.984,108.486 h1.52
  text "X" at 329.348,108.486 h1.52
  text "OTHER" at 340.168,104.873 h1.52
  text "PTH COPPER THICKNESS:" at 289.761,104.783 h1.52
  text "X" at 318.697,104.783 h1.52
  text "20-30 um" at 321.948,104.783 h1.52
  text "BOARD FINISH:" at 287.87,101.034 h1.52
  text "SILKSCREEN:" at 291.812,98.237 h1.52
  text "X" at 316.14,98.237 h1.52
  text "TOP" at 319.112,98.237 h1.52
  text "X" at 329.094,98.237 h1.52
  text "BOTTOM" at 332.091,98.237 h1.52
  text "SILKSCREEN COLOR:" at 291.812,94.295 h1.52
  text "X" at 316.115,94.295 h1.52
  text "WHITE" at 319.112,94.295 h1.52
  text "OTHER" at 332.091,94.295 h1.52
  text "X" at 319.442,90.652 h1.52
  text "BLUE" at 322.439,90.652 h1.52
  text "OTHER" at 338.136,90.652 h1.52
  text "SOLDER RESIST COLOR:" at 291.812,90.477 h1.52
  text "X" at 319.442,86.734 h1.52
  text "MATTE" at 322.439,86.734 h1.52
  text "SEMI-GLOSS" at 338.125,86.717 h1.52
  text "IMMERSION GOLD (ENIG)" at 314.819,82.345 h1.52
  text "ENEPIG" at 348.793,82.162 h1.52
  text "SURFACE FINISH:" at 287.87,82.136 h1.52
  text "X" at 310.298,82.136 h1.52
  text "IMM. TIN/SILVER OR EQUIV" at 296.24,78.649 h1.52
  text "OTHER" at 332.599,78.549 h1.52
  text "ARRAY/PANEL:" at 287.87,74.602 h1.52
  text "CUT AND TRIM PER M1 BOARD OUTLINE" at 314.819,74.393 h1.52
  text "N.C. ROUTE" at 314.819,70.94 h1.52
  text "X" at 332.295,70.94 h1.52
  text "V. SCORE" at 336.816,70.94 h1.52
  text "CERTIFICATION:" at 287.87,67.66 h1.52
  text "MATERIALS AND WORKMANSHIP FOR ALL PCBS" at 306.285,67.66 h1.52
  text "TO MEET OR EXCEED THE REQUIREMENTS OF:" at 306.285,65.271 h1.52
  text "X" at 297.078,62.003 h1.52
  text "ANSI IPC-A-600F CLASS ->" at 300.329,62.003 h1.52
  text "X" at 342.188,62.003 h1.52
  text "2" at 344.982,62.003 h1.52
  text "1" at 336.981,61.965 h1.52
  text "3" at 353.973,61.965 h1.52
  text "X" at 317.702,58.252 h1.52
  text "RoHS" at 320.953,58.252 h1.52
  text "OTHER" at 337.321,58.252 h1.52
  text "PER ORDER" at 347.407,58.252 h1.52
  text "ALL BOARDS MUST MEET OR EXCEED UL94-V0 REQUIREMENTS." at 288.569,54.345 h1.52
  text "PCB MUST BEAR THE UL94V-0 UL REGISTERED MATERIAL ID NUMBER" at 288.569,51.397 h1.52
  text "ADDITIONAL REQUIREMENTS:" at 287.87,47.094 h1.52
  text "MICROSECTION:" at 289.769,44.373 h1.52
  text "YES" at 312.775,44.373 h1.52
  text "REQUIRED" at 334.657,40.707 h1.52
  text "BARE BOARD ELEC. TEST:" at 289.769,40.634 h1.52
  text "NONE" at 322.935,40.634 h1.52
  text "X" at 331.66,40.634 h1.52
  text "PER ORDER" at 349.693,40.634 h1.52
  text "XX MIL VIAS REQUIRE NON-CONDUCTIVE FILL AND PLANARIZE" at 294.04,35.428 h1.5
  text "XX MIL VIAS REQUIRE CONDUCTIVE FILL AND PLANARIZE" at 294.243,32.787 h1.52
  text "OUTER XX MIL VIAS REQUIRE 50 OHM SINGLE-ENDED IMPEDANCE" at 294.218,28.637 h1.47
  text "LAYER 2 & 3 (INNER LAYERS) XX MIL WIDE, XX MIL SPACE / TRACES REQUIRE 100 OHM DIFFERENTIAL IMPEDANCE" at 294.015,22.65 h1.52
M11 Gerber Information:
  lines w0.254: -7.417,-23.626 160.223,-23.626 ; -7.417,-18.462 160.274,-18.462 ; -7.417,-13.297 -7.417,-28.791 94.31,-28.791 160.274,-28.791 160.274,-13.297 -7.404,-13.297 -7.404,-28.791 32.614,-28.791 ; 55.194,-28.791 55.194,-13.297 ; 87.376,-18.462 87.376,-13.297 ; 108.712,-18.462 108.712,-13.297 ; 124.511,-28.956 124.511,-23.804
  text "ALL ARTWORK VIEWED FROM TOP SIDE" at -5.804,-16.654 h1.52
  text "BOARD #:" at 57.099,-16.654 h1.52
  text ".PRJ_Number" at 70.955,-16.654 h1.52
  text "REV:" at 92.405,-16.654 h1.52
  text ".PCB_Rev" at 99.809,-16.654 h1.52
  text "SVN REV:" at 113.69,-16.654 h1.52
  text ".VersionControl_RevNumber" at 126.543,-16.654 h1.52
  text "LAYER NAME =" at -5.804,-21.806 h1.52
  text "PLOT NAME =" at -5.804,-27.034 h1.52
  text ".plot_File_Name" at 14.656,-27.034 h1.52
  text "GENERATED    :" at 57.15,-27.034 h1.52
  text ".Print_Date" at 79.235,-27.034 h1.52
  text ".Print_Time" at 97.752,-27.034 h1.52
  text "TEXAS INSTRUMENTS" at 129.87,-27.034 h1.52
M12 Stackup:
  drawing of 295 lines, arcs and shapes, not listed
  text ".Layer_Name" at 95.25,78 h1.52
  text "Layer" at 96.715,74.48 h1.52
  text "Name" at 107.126,74.48 h1.52
  text "Material" at 130.996,74.48 h1.52
  text "Thickness" at 152.834,74.48 h1.52
  text "Constant" at 169.34,74.48 h1.52
  text "Board Layer Stack" at 183.814,74.48 h1.52
  text "1" at 96.715,71.432 h1.52
  text "Top Overlay" at 107.126,71.432 h1.52
  text "2" at 96.715,68.384 h1.52
  text "Top Solder" at 107.126,68.384 h1.52
  text "Solder Resist" at 130.996,68.384 h1.52
  text "0.40mil" at 152.834,68.384 h1.52
  text "3.5" at 169.34,68.384 h1.52
  text "3" at 96.715,65.336 h1.52
  text "Top Layer" at 107.126,65.336 h1.52
  text "Copper" at 130.996,65.336 h1.52
  text "2.74mil" at 152.834,65.336 h1.52
  text "4" at 96.715,62.288 h1.52
  text "Dielectric 1" at 107.126,62.288 h1.52
  text "FR-4" at 130.996,62.288 h1.52
  text "8.00mil" at 152.834,62.288 h1.52
  text "4.2" at 169.34,62.288 h1.52
  text "5" at 96.715,59.24 h1.52
  text "Signal Layer 1" at 107.126,59.24 h1.52
  text "Copper" at 130.996,59.24 h1.52
  text "1.40mil" at 152.834,59.24 h1.52
  text "6" at 96.715,56.192 h1.52
  text "Dielectric 2" at 107.126,56.192 h1.52
  text "FR-4" at 130.996,56.192 h1.52
  text "37.42mil" at 152.834,56.192 h1.52
  text "4.2" at 169.34,56.192 h1.52
  text "7" at 96.715,53.144 h1.52
  text "Signal Layer 2" at 107.126,53.144 h1.52
  text "Copper" at 130.996,53.144 h1.52
  text "1.40mil" at 152.834,53.144 h1.52
  text "8" at 96.715,50.096 h1.52
  text "Dielectric 3" at 107.126,50.096 h1.52
  text "FR-4" at 130.996,50.096 h1.52
  text "8.00mil" at 152.834,50.096 h1.52
  text "4.2" at 169.34,50.096 h1.52
  text "9" at 96.715,47.048 h1.52
  text "Bottom Layer" at 107.126,47.048 h1.52
  text "Copper" at 130.996,47.048 h1.52
  text "2.74mil" at 152.834,47.048 h1.52
  text "10" at 96.715,44 h1.52
  text "Bottom Solder" at 107.126,44 h1.52
  text "Solder Resist" at 130.996,44 h1.52
  text "0.40mil" at 152.834,44 h1.52
  text "3.5" at 169.34,44 h1.52
  text "11" at 96.715,40.952 h1.52
  text "Bottom Overlay" at 107.126,40.952 h1.52
M13 Component Bodies Top:
  text ".Layer_Name" at 14.656,-21.806 h1.52
M14 Component Bodies Bottom:
  text ".Layer_Name" at 14.656,-21.806 h1.52
M15 Courtyards Top:
  text ".Layer_Name" at 14.656,-21.806 h1.52
M16 Courtyards Bottom:
  text ".Layer_Name" at 14.656,-21.806 h1.52
Drill Drawing:
  lines w0.254: 96.426,4.263 97.129,4.615 97.832,4.263 97.481,4.966 97.832,5.669 97.129,5.317 96.426,5.669 96.778,4.966 96.426,4.263 ; 96.426,8.831 97.832,8.831 97.129,7.426 96.426,8.831 ; 96.426,10.939 96.778,10.939 96.778,10.588 97.481,10.588 97.481,10.939 97.832,10.939 97.832,11.642 97.481,11.642 97.481,11.993 96.778,11.993 96.778,11.642 96.426,11.642 96.426,10.939 ; 96.426,13.75 97.832,13.75 97.832,15.156 96.426,15.156 96.426,13.75 ; 96.426,17.615 97.129,16.913 97.832,17.615 97.129,18.318 96.426,17.615 ; 96.426,20.075 97.832,20.075 97.832,21.48 96.426,21.48 96.426,20.075 ; 96.426,23.589 96.778,23.589 97.129,23.237 97.481,23.589 97.832,23.589 97.481,23.94 97.832,24.291 97.481,24.291 97.129,24.643 96.778,24.291 96.426,24.291 96.778,23.94 96.426,23.589 ; 96.708,20.356 97.551,20.356 97.551,21.199 96.708,21.199 96.708,20.356
  lines w0.305: 95.152,3.315 163.808,3.315 ; 95.152,25.451 163.808,25.451 ; 103.738,0.152 103.738,28.613 ; 112.175,0.152 112.175,28.613 ; 128.341,0.152 128.341,28.613 ; 134.925,0.152 134.925,28.613 ; 144.456,0.152 144.456,28.613 ; 95.152,0.152 163.808,0.152 163.808,28.613 95.152,28.613 95.152,0.152
  text "Symbol" at 97.05,26.399 h1.83
  text "Quantity" at 104.687,26.399 h1.83
  text "Finished Hole Size" at 113.123,26.399 h1.83
  text "Plated" at 129.29,26.399 h1.83
  text "Hole Type" at 135.874,26.399 h1.83
  text "Drill Layer Pair" at 145.405,26.399 h1.83
  text "2" at 104.687,23.237 h1.52
  text "40.00mil (1.016mm)" at 113.123,23.237 h1.52
  text "NPTH" at 129.29,23.237 h1.52
  text "Round" at 135.874,23.237 h1.52
  text "Top Layer - Bottom Layer" at 145.405,23.237 h1.52
  text "10" at 104.687,20.075 h1.52
  text "7.87mil (0.200mm)" at 113.123,20.075 h1.52
  text "PTH" at 129.29,20.075 h1.52
  text "Round" at 135.874,20.075 h1.52
  text "Top Layer - Bottom Layer" at 145.405,20.075 h1.52
  text "426" at 104.687,16.913 h1.52
  text "10.00mil (0.254mm)" at 113.123,16.913 h1.52
  text "PTH" at 129.29,16.913 h1.52
  text "Round" at 135.874,16.913 h1.52
  text "Top Layer - Bottom Layer" at 145.405,16.913 h1.52
  text "15" at 104.687,13.75 h1.52
  text "40.00mil (1.016mm)" at 113.123,13.75 h1.52
  text "PTH" at 129.29,13.75 h1.52
  text "Round" at 135.874,13.75 h1.52
  text "Top Layer - Bottom Layer" at 145.405,13.75 h1.52
  text "6" at 104.687,10.588 h1.52
  text "70.00mil (1.778mm)" at 113.123,10.588 h1.52
  text "PTH" at 129.29,10.588 h1.52
  text "Round" at 135.874,10.588 h1.52
  text "Top Layer - Bottom Layer" at 145.405,10.588 h1.52
  text "6" at 104.687,7.426 h1.52
  text "127.95mil (3.250mm)" at 113.123,7.426 h1.52
  text "PTH" at 129.29,7.426 h1.52
  text "Round" at 135.874,7.426 h1.52
  text "Top Layer - Bottom Layer" at 145.405,7.426 h1.52
  text "2" at 104.687,4.263 h1.52
  text "144.00mil (3.658mm)" at 113.123,4.263 h1.52
  text "PTH" at 129.29,4.263 h1.52
  text "Round" at 135.874,4.263 h1.52
  text "Top Layer - Bottom Layer" at 145.405,4.263 h1.52
  text "467 Total" at 104.687,1.101 h1.52
  text ".Layer_Name" at 14.656,-21.806 h1.52
Mechanical 17:
  lines w0.25: -5,60 76,60 ; 8,60 10,60 ; 48.75,10 85,25 ; 48.75,40 85,25 ; 48.75,80 85,95 ; 48.75,110 85,95 ; 55,14 85,14 ; 55,25 85,25 ; 55,36 85,36 ; 55,84 85,84 ; 55,95 85,95 ; 55,106 85,106 ; 9,59 9,61 9,59

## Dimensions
-0.5,90 to 24.5,120 on M2 Board Dimensions
-0.5,30 to -0.5,90 on M2 Board Dimensions
-0.5,0 to -0.5,30 on M2 Board Dimensions
25,-1.5 to 85,-0.5 on M2 Board Dimensions
0,-0.5 to 25,-0.5 on M2 Board Dimensions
